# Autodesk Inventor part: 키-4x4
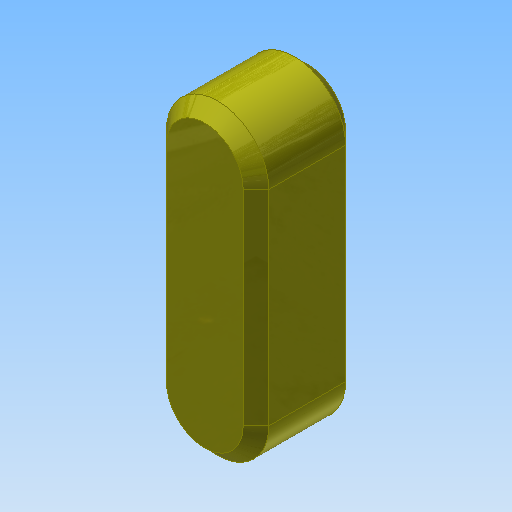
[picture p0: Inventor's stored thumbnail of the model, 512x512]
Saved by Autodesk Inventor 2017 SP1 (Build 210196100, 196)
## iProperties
Created: 2015-12
Part Number: 키-4x4
Document SubType Name: Modeling
Designer: mdu
Density: 7.86 g/cm^3
Material: 강철, 연강
Mass: 1.34709 g
Surface Area: 1.86014 cm^2
Volume: 0.171386 cm^3
Appearance: 노란색
Author: mdu
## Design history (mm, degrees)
sketch "스케치1"
  geometry: L1 (-2, -10)-(-2, -2) reference; L2 (2, -2)-(2, -10) reference; A1 r 2 centre (0, -2) between (2, -2) and (-2, -2) reference; A2 r 2 centre (0, -10) between (-2, -10) and (2, -10) reference; 1 further point
extrude "돌출1" new body sketch "스케치1" distance "d0" = 4; taper "d1" = 0 deg
chamfer "모따기1" distance "d2" = 0.5; stored, may be unused: second distance "d3" = 2, angle "d4" = 45 deg
node "솔리드1"
node "참조1"
